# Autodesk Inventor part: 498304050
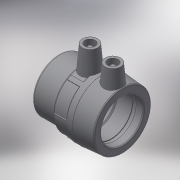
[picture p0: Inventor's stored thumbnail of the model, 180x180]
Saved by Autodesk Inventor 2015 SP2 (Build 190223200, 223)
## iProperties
Created: 2017-06
Part Number: 498304050
Material: Generic
Description: PLASSON WELDING CAP FOR TAPPING SADDLE TYPE-B
Document SubType Name: Modeling
Designer: KIM
Density: 1 g/cm^3
Appearance: Default
Author: KIM
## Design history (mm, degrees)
derived "498304_2.ipt"
feature "Solid1::498304_2.ipt"
tag "TaggingFeature1"
body "Solid1"
other parameters: "d7" = 1.86, "d8" = 23.1, "d10" = 1.24, "d11" = 13.2, "d12" = 168 deg, "d13" = 4.4, "d14" = 48.6, "d15" = 54, "d16" = 15, "d17" = 36.5, "d18" = 1, "d20" = 5 deg, "d21" = 48.6, "d22" = 15, "d26" = 5 deg, "d27" = 4, "d29" = 14, "d30" = 0, "d31" = 4, "d33" = 14, "d34" = 0, "d46" = 3, "d47" = 0, "d48" = 3, "d49" = 0, "d50" = 73, "d51" = 62, "d52" = 68.2, "d53" = 70.68, "d54" = 66, "d55" = 135 deg, "d57" = 46.17, "d58" = 43.74, "d59" = 71.54, "d60" = 40.3, "d61" = 10.95, "d62" = 2.43, "d63" = 4.86, "d64" = 2.43, "d66" = 0, "d67" = 60 deg, "d69" = 360 deg, "d71" = 3.1, "d74" = 4.34, "d_" = 48.6, "L_" = 66, "D_" = 62, "A_" = 54, "H_" = 73
